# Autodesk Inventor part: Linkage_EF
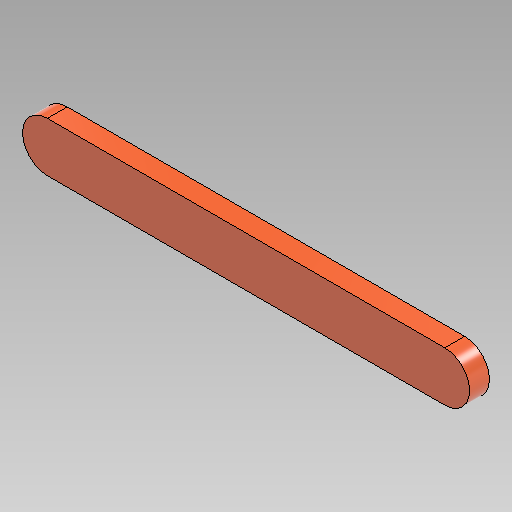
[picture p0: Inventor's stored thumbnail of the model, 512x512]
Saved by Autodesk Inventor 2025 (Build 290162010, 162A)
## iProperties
Created: 2024-10
Part Number: Linkage_EF
Material: Generic
Document SubType Name: Modeling
Designer: Dennis
Density: 1 g/cm^3
Appearance: Smooth - Light Orange
Mass: 0.43927 g
Surface Area: 6.30686 cm^2
Volume: 0.43927 cm^3
Author: Dennis
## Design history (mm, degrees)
sketch "Sketch1"
  geometry: L1 (0, 0)-(40, 0); L2 (0, -2.5)-(40, -2.5); L3 (40, 2.5)-(0, 2.5); A1 r 2.5 centre (0, 0) between (0, 2.5) and (0, -2.5); A2 r 2.5 centre (40, 0) between (40, -2.5) and (40, 2.5); 1 further point
  constraints: 8 end point, 4 point on circle, 4 tangent, 2 centre point, 1 horizontal, 1 midpoint, 1 parallel
  dimensions: "d0" = 5 distance between parallel lines of L2 L3 (= w_); "d1" = 40 distance of L1.start L1.end (= EF_)
extrude "Extrusion1" new body sketch "Sketch1" stored distance "d2" = 2 (= t_); taper "d3" = 0 deg
body "Solid1"
other parameters: "EF_" = 40 [user parameter; used in 1 equation term], "w_" = 5 [user parameter; used in 1 equation term], "t_" = 2 [user parameter; used in 1 equation term]
